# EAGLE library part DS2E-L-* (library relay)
DS-RELAYS HIGHLY SENSITIVE 1500 V FCC SURGE NAiS WITHSTANDING MINIATURE RELAY Source: http://www.mew-europe.com/.. en_ds_61005_0001.pdf
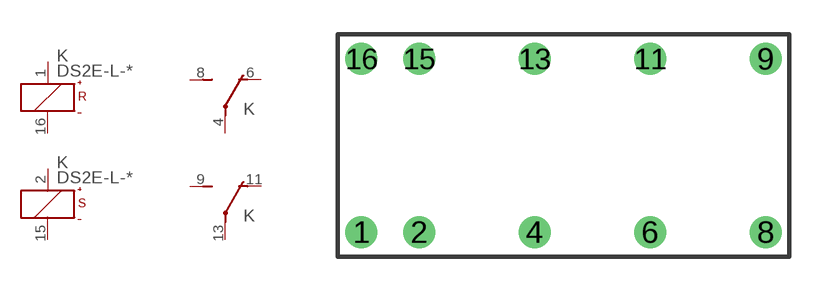
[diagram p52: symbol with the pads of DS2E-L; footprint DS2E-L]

Designator prefix K; gates 1=K+-R 2=K+-S 3=U 4=U

## DS2E-L-1.5V (OC_FARNELL: unknown; OC_NEWARK: unknown), DS2E-L-3V (OC_FARNELL: unknown; OC_NEWARK: unknown), DS2E-L-5V (MF: AROMAT/ MATSUSHITA; MPN: DS2E-SL-DC5V; OC_FARNELL: unknown; OC_NEWARK: 10C5815), DS2E-L-6V (OC_FARNELL: unknown; OC_NEWARK: unknown), DS2E-L-9V (OC_FARNELL: unknown; OC_NEWARK: unknown), DS2E-L-12V (OC_FARNELL: unknown; OC_NEWARK: unknown), DS2E-L-24V (MF: AROMAT/ MATSUSHITA; MPN: DS2E-SL-DC24V; OC_FARNELL: unknown; OC_NEWARK: 10C5812), DS2E-L-48V (OC_FARNELL: unknown; OC_NEWARK: unknown)  [DS2E-L]
1  1:+  pas
2  2:+  pas
4  3:P  pas
6  3:O  pas
8  3:S  pas
9  4:S  pas
11  4:O  pas
13  4:P  pas
15  2:-  pas
16  1:-  pas

## Footprint DS2E-L (pad centres in mm)
DS-RELAYS HIGHLY SENSITIVE 1500 V FCC SURGE NAiS WITHSTANDING MINIATURE RELAY Source: http://www.mew-europe.com/.. en_ds_61005_0001.pdf
drill 0.9 round: 1 -8.89,-3.81; 2 -6.35,-3.81; 4 -1.27,-3.81; 6 3.81,-3.81; 8 8.89,-3.81; 9 8.89,3.81; 11 3.81,3.81; 13 -1.27,3.81; 15 -6.35,3.81; 16 -8.89,3.81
